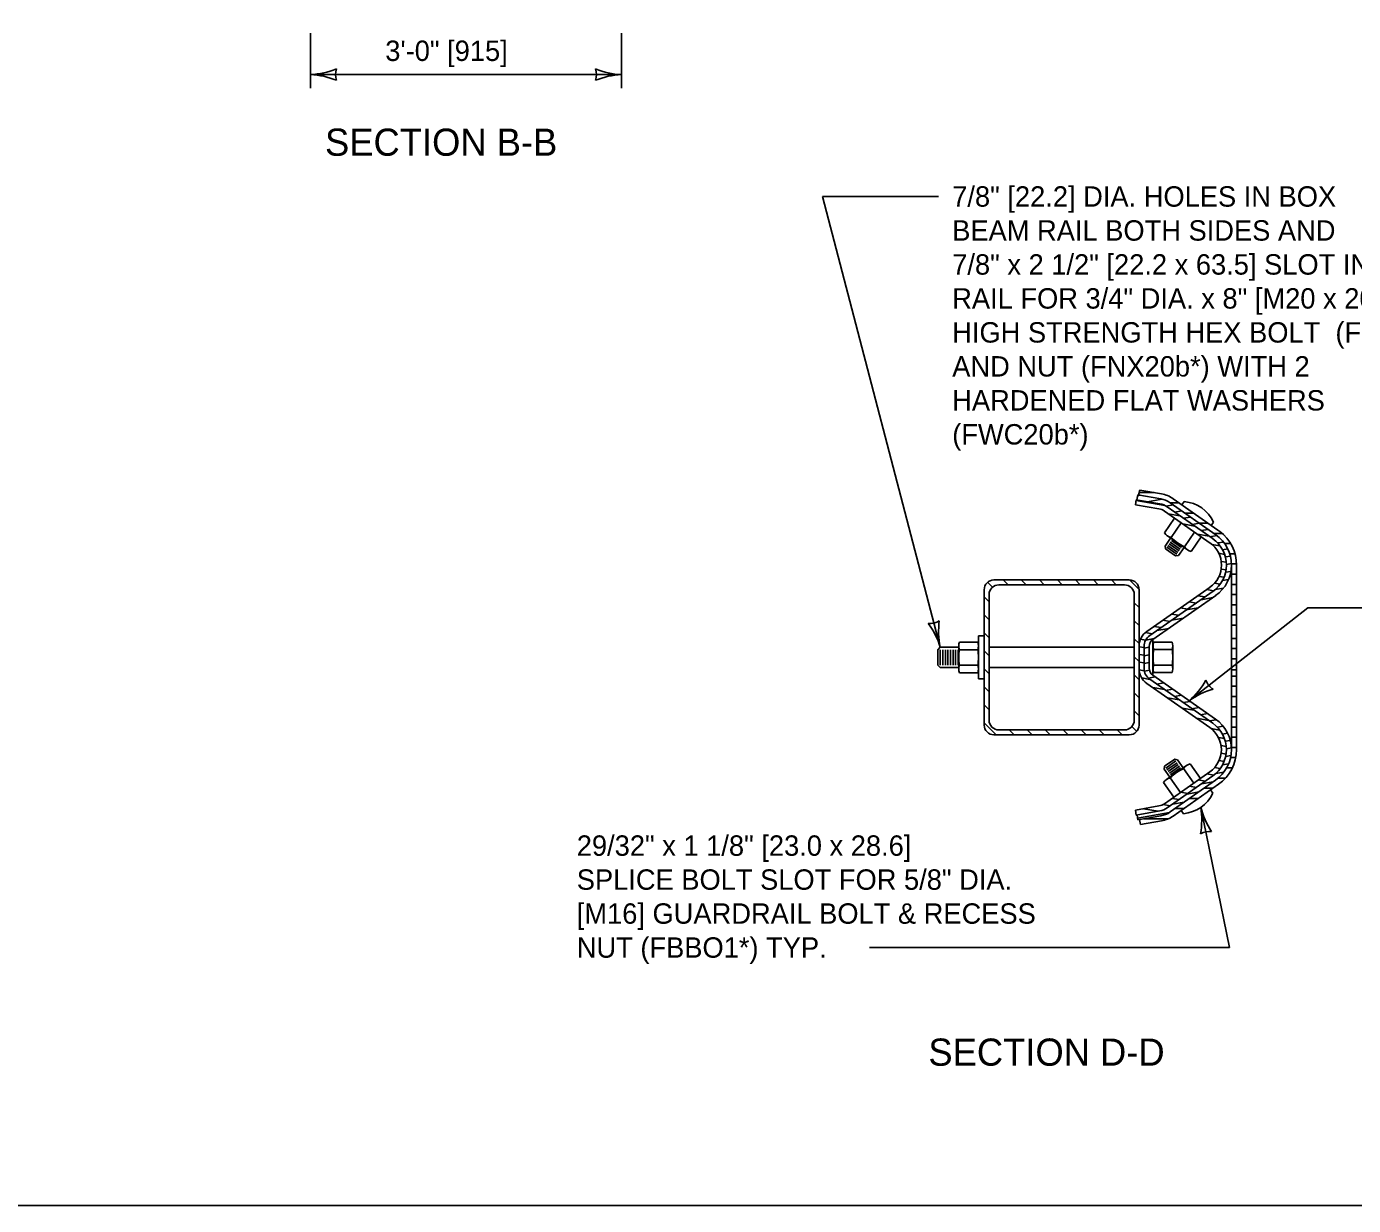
# Model space of a CAD drawing. Extents: x 49991.4 to 50021, y 49987.6 to 50011.4.
# Drawn here: x 50005.459 to 50009.364, y 49987.799 to 49991.269 of the extents above; entities that cross this region are included whole.
import ezdxf

# ---------------------------------------------------------------- set-up
doc = ezdxf.new("R2010")
doc.units = 0
for name, color, linetype in [('Level 1', 7, 'Continuous'), ('Level 2', 7, 'Continuous'), ('Level 3', 7, 'Continuous')]:
    doc.layers.add(name, color=color, linetype=linetype)

msp = doc.modelspace()

# ---------------------------------------------------------------- linework, layer by layer
at = {"layer": 'Level 1'}
for p, q in [((50008.7248, 49989.876), (50008.7222, 49989.8614)), ((50008.7244, 49989.874), (50008.8085, 49989.8592)), ((50008.7248, 49989.876), (50008.7941, 49989.8639)), ((50008.7293, 49989.8902), (50008.7268, 49989.8756)), ((50008.7288, 49989.8877), (50008.7362, 49989.889)), ((50008.7293, 49989.8902), (50008.7967, 49989.8785)), ((50008.7318, 49989.8898), (50008.7349, 49989.9043)), ((50008.7333, 49989.8968), (50008.7777, 49989.8968)), ((50008.7349, 49989.9043), (50008.7992, 49989.893)), ((50008.7576, 49989.8702), (50008.8, 49989.8777)), ((50008.8332, 49989.879), (50008.9647, 49989.7867)), ((50008.7222, 49989.8614), (50008.7916, 49989.8493)), ((50008.8077, 49989.8426), (50008.9421, 49989.7483)), ((50008.8123, 49989.8573), (50008.8332, 49989.861)), ((50008.8162, 49989.8548), (50008.9507, 49989.7604)), ((50008.8189, 49989.8348), (50008.8533, 49989.8287)), ((50008.8247, 49989.8669), (50008.9592, 49989.7725)), ((50008.8248, 49989.8668), (50008.8506, 49989.8668)), ((50008.8383, 49989.8393), (50008.8589, 49989.8429)), ((50008.8662, 49989.8704), (50008.8593, 49989.8607)), ((50008.8676, 49989.8368), (50008.8933, 49989.8368)), ((50008.8376, 49989.8216), (50008.8075, 49989.7786)), ((50008.8271, 49989.7648), (50008.8572, 49989.8078)), ((50008.8619, 49989.8046), (50008.8963, 49989.7985)), ((50008.864, 49989.8212), (50008.8846, 49989.8249)), ((50008.8898, 49989.8032), (50008.9103, 49989.8068)), ((50008.9104, 49989.8068), (50008.9361, 49989.8068)), ((50008.9523, 49989.8102), (50008.9454, 49989.8003)), ((50008.8094, 49989.7394), (50008.826, 49989.7632)), ((50008.8751, 49989.7289), (50008.8163, 49989.7701)), ((50008.8575, 49989.735), (50008.828, 49989.7556)), ((50008.8665, 49989.7373), (50008.8965, 49989.7803)), ((50008.9162, 49989.7665), (50008.8862, 49989.7236)), ((50008.905, 49989.7744), (50008.9393, 49989.7683)), ((50008.9155, 49989.7851), (50008.9361, 49989.7887)), ((50008.9413, 49989.7671), (50008.9616, 49989.7707)), ((50008.9532, 49989.7768), (50008.9776, 49989.7768)), ((50008.9592, 49989.7725), (50008.9585, 49989.7731)), ((50008.9647, 49989.7867), (50008.9703, 49989.7829)), ((50008.8094, 49989.7394), (50008.8108, 49989.731)), ((50008.8403, 49989.7104), (50008.8108, 49989.731)), ((50008.8438, 49989.7153), (50008.8143, 49989.736)), ((50008.8472, 49989.7202), (50008.8177, 49989.7409)), ((50008.8506, 49989.7251), (50008.8212, 49989.7458)), ((50008.8541, 49989.73), (50008.8246, 49989.7507)), ((50008.8487, 49989.7119), (50008.8654, 49989.7357)), ((50008.9473, 49989.7444), (50008.9712, 49989.7401)), ((50008.9644, 49989.7486), (50008.9812, 49989.7515)), ((50008.9675, 49989.7182), (50008.9846, 49989.7152)), ((50008.9789, 49989.7285), (50008.9941, 49989.7312)), ((50008.985, 49989.7468), (50009.0024, 49989.7468)), ((50008.9999, 49989.7168), (50009.0153, 49989.7168)), ((50008.8487, 49989.7119), (50008.8403, 49989.7104)), ((50008.9747, 49989.6943), (50008.9897, 49989.6917)), ((50008.9872, 49989.7074), (50009.0017, 49989.7099)), ((50008.9903, 49989.6854), (50009.0049, 49989.6879)), ((50009.0051, 49989.6834), (50009.0049, 49989.1403)), ((50009.0051, 49989.6868), (50009.0197, 49989.6868)), ((50009.0199, 49989.6834), (50009.0197, 49989.1403)), ((50008.7043, 49989.6399), (50008.3059, 49989.6399)), ((50008.3478, 49989.6255), (50008.3334, 49989.6399)), ((50008.4008, 49989.6255), (50008.3864, 49989.6399)), ((50008.4539, 49989.6255), (50008.4395, 49989.6399)), ((50008.5069, 49989.6255), (50008.4925, 49989.6399)), ((50008.5599, 49989.6255), (50008.5455, 49989.6399)), ((50008.613, 49989.6255), (50008.5986, 49989.6399)), ((50008.666, 49989.6255), (50008.6516, 49989.6399)), ((50008.733, 49989.6115), (50008.7046, 49989.6399)), ((50008.9682, 49989.6503), (50008.9831, 49989.6477)), ((50008.9746, 49989.6718), (50008.9891, 49989.6692)), ((50008.9787, 49989.6381), (50008.9964, 49989.6413)), ((50008.9879, 49989.6623), (50009.0034, 49989.6651)), ((50009.0051, 49989.6568), (50009.0199, 49989.6568)), ((50008.2771, 49989.6111), (50008.2771, 49989.2127)), ((50008.3016, 49989.6187), (50008.2872, 49989.6331)), ((50008.6899, 49989.6255), (50008.3203, 49989.6255)), ((50008.7331, 49989.2127), (50008.7331, 49989.6111)), ((50008.9422, 49989.6188), (50008.7562, 49989.4886)), ((50008.9507, 49989.6066), (50008.7647, 49989.4765)), ((50008.932, 49989.6115), (50008.9524, 49989.6079)), ((50008.9549, 49989.6301), (50008.9715, 49989.6271)), ((50008.9574, 49989.6118), (50008.9817, 49989.6161)), ((50009.0051, 49989.6268), (50009.0199, 49989.6268)), ((50008.2915, 49989.5758), (50008.2771, 49989.5902)), ((50008.2915, 49989.5967), (50008.2915, 49989.2271)), ((50008.7187, 49989.2271), (50008.7187, 49989.5967)), ((50008.7331, 49989.5585), (50008.7187, 49989.5729)), ((50008.9592, 49989.5945), (50008.7732, 49989.4643)), ((50008.8804, 49989.5754), (50008.9009, 49989.5718)), ((50008.9062, 49989.5935), (50008.9267, 49989.5899)), ((50008.9154, 49989.5818), (50008.9497, 49989.5878)), ((50008.9585, 49989.5938), (50008.9592, 49989.5945)), ((50009.0051, 49989.5968), (50009.0199, 49989.5968)), ((50009.0051, 49989.5668), (50009.0199, 49989.5668)), ((50008.2915, 49989.5228), (50008.2771, 49989.5372)), ((50008.2771, 49989.2994), (50008.2771, 49989.5244)), ((50008.7331, 49989.5054), (50008.7187, 49989.5198)), ((50008.803, 49989.5213), (50008.8236, 49989.5177)), ((50008.8288, 49989.5393), (50008.8494, 49989.5357)), ((50008.8289, 49989.5214), (50008.8634, 49989.5274)), ((50008.8546, 49989.5574), (50008.8751, 49989.5538)), ((50008.8721, 49989.5516), (50008.9065, 49989.5576)), ((50009.0051, 49989.5368), (50009.0199, 49989.5368)), ((50008.2915, 49989.4697), (50008.2771, 49989.4841)), ((50008.7521, 49989.4851), (50008.772, 49989.4816)), ((50008.7772, 49989.5033), (50008.7978, 49989.4996)), ((50008.7857, 49989.4912), (50008.8203, 49989.4972)), ((50009.0051, 49989.5068), (50009.0199, 49989.5068)), ((50008.148, 49989.4419), (50008.1405, 49989.4344)), ((50008.2023, 49989.4419), (50008.148, 49989.4419)), ((50008.2023, 49989.4457), (50008.2023, 49989.3783)), ((50008.2582, 49989.4569), (50008.2042, 49989.4569)), ((50008.2601, 49989.4457), (50008.2601, 49989.3783)), ((50008.2606, 49989.4749), (50008.2771, 49989.4749)), ((50008.2606, 49989.3489), (50008.2606, 49989.4749)), ((50008.2915, 49989.4419), (50008.7187, 49989.4419)), ((50008.7331, 49989.4524), (50008.7187, 49989.4668)), ((50008.7331, 49989.4441), (50008.7331, 49989.4119)), ((50008.7331, 49989.4433), (50008.7479, 49989.4407)), ((50008.7374, 49989.4651), (50008.7524, 49989.4625)), ((50008.7479, 49989.4441), (50008.7479, 49989.4119)), ((50008.7479, 49989.4393), (50008.7627, 49989.4419)), ((50008.7527, 49989.4627), (50008.7771, 49989.4671)), ((50008.7627, 49989.4441), (50008.7627, 49989.4119)), ((50008.7738, 49989.3592), (50008.7738, 49989.4647)), ((50008.7743, 49989.4458), (50008.7743, 49989.3785)), ((50008.7762, 49989.4571), (50008.8303, 49989.4571)), ((50008.8321, 49989.4458), (50008.8321, 49989.3785)), ((50009.005, 49989.4678), (50009.0198, 49989.4678)), ((50008.1405, 49989.4344), (50008.1405, 49989.3894)), ((50008.148, 49989.4344), (50008.148, 49989.3894)), ((50008.1555, 49989.4344), (50008.1555, 49989.3894)), ((50008.163, 49989.4344), (50008.163, 49989.3894)), ((50008.1705, 49989.4344), (50008.1705, 49989.3894)), ((50008.178, 49989.4344), (50008.178, 49989.3894)), ((50008.1855, 49989.4344), (50008.1855, 49989.3894)), ((50008.193, 49989.4344), (50008.193, 49989.3894)), ((50008.2005, 49989.4344), (50008.2005, 49989.3894)), ((50008.2583, 49989.4346), (50008.2041, 49989.4346)), ((50008.2915, 49989.4167), (50008.2771, 49989.4311)), ((50008.733, 49989.3995), (50008.7187, 49989.4138)), ((50008.7331, 49989.4207), (50008.7479, 49989.4181)), ((50008.7331, 49989.4119), (50008.7331, 49989.3798)), ((50008.7479, 49989.4167), (50008.7627, 49989.4193)), ((50008.7479, 49989.4119), (50008.7479, 49989.3798)), ((50008.7627, 49989.4119), (50008.7627, 49989.3798)), ((50008.7761, 49989.4348), (50008.8303, 49989.4348)), ((50009.005, 49989.4378), (50009.0198, 49989.4378)), ((50009.005, 49989.4078), (50009.0198, 49989.4078)), ((50008.148, 49989.3819), (50008.1405, 49989.3894)), ((50008.2023, 49989.3819), (50008.148, 49989.3819)), ((50008.2583, 49989.3893), (50008.2041, 49989.3893)), ((50008.2582, 49989.3669), (50008.2042, 49989.3669)), ((50008.2915, 49989.3637), (50008.2771, 49989.3781)), ((50008.2915, 49989.3819), (50008.7187, 49989.3819)), ((50008.7331, 49989.3981), (50008.7479, 49989.3955)), ((50008.7334, 49989.3754), (50008.7485, 49989.3728)), ((50008.7479, 49989.3941), (50008.7627, 49989.3967)), ((50008.7487, 49989.3717), (50008.7633, 49989.3743)), ((50008.7761, 49989.3894), (50008.8303, 49989.3894)), ((50008.7762, 49989.3671), (50008.8303, 49989.3671)), ((50009.005, 49989.3749), (50009.0198, 49989.3749)), ((50008.2606, 49989.3489), (50008.2771, 49989.3489)), ((50008.2915, 49989.3106), (50008.2771, 49989.325)), ((50008.7331, 49989.3463), (50008.7187, 49989.3607)), ((50008.741, 49989.3515), (50008.7649, 49989.3473)), ((50008.7562, 49989.3353), (50008.9412, 49989.2058)), ((50008.7603, 49989.3511), (50008.7802, 49989.3547)), ((50008.7647, 49989.3474), (50008.9497, 49989.2179)), ((50008.7732, 49989.3596), (50008.9582, 49989.2301)), ((50008.7854, 49989.333), (50008.806, 49989.3366)), ((50009.005, 49989.3568), (50009.0198, 49989.3568)), ((50009.005, 49989.3268), (50009.0198, 49989.3268)), ((50008.7331, 49989.2933), (50008.7187, 49989.3077)), ((50008.7734, 49989.3232), (50008.808, 49989.3171)), ((50008.8111, 49989.3149), (50008.8318, 49989.3186)), ((50008.8166, 49989.293), (50008.8511, 49989.2869)), ((50008.8369, 49989.2969), (50008.8576, 49989.3005)), ((50009.005, 49989.2968), (50009.0198, 49989.2968)), ((50008.2915, 49989.2576), (50008.2771, 49989.272)), ((50008.7331, 49989.2403), (50008.7187, 49989.2547)), ((50008.8597, 49989.2628), (50008.8943, 49989.2567)), ((50008.8627, 49989.2788), (50008.8833, 49989.2825)), ((50008.8885, 49989.2608), (50008.9091, 49989.2644)), ((50008.9142, 49989.2427), (50008.9349, 49989.2464)), ((50009.0049, 49989.2668), (50009.0197, 49989.2668)), ((50008.3121, 49989.1839), (50008.2771, 49989.219)), ((50008.7262, 49989.1941), (50008.7118, 49989.2085)), ((50008.9028, 49989.2326), (50008.9374, 49989.2265)), ((50008.94, 49989.2247), (50008.9604, 49989.2283)), ((50008.9634, 49989.2062), (50008.9804, 49989.2092)), ((50009.0049, 49989.2368), (50009.0197, 49989.2368)), ((50009.0049, 49989.2068), (50009.0197, 49989.2068)), ((50008.3059, 49989.1839), (50008.7043, 49989.1839)), ((50008.3203, 49989.1983), (50008.6899, 49989.1983)), ((50008.3651, 49989.1839), (50008.3507, 49989.1983)), ((50008.4182, 49989.1839), (50008.4038, 49989.1983)), ((50008.4712, 49989.1839), (50008.4568, 49989.1983)), ((50008.5242, 49989.1839), (50008.5098, 49989.1983)), ((50008.5773, 49989.1839), (50008.5629, 49989.1983)), ((50008.6303, 49989.1839), (50008.6159, 49989.1983)), ((50008.6833, 49989.1839), (50008.6689, 49989.1983)), ((50008.9455, 49989.2025), (50008.9702, 49989.1982)), ((50008.9668, 49989.1762), (50008.984, 49989.1731)), ((50008.9782, 49989.1862), (50008.9934, 49989.1889)), ((50009.0049, 49989.1768), (50009.0197, 49989.1768)), ((50008.9743, 49989.1522), (50008.9894, 49989.1496)), ((50008.9745, 49989.1296), (50008.9891, 49989.1271)), ((50008.9868, 49989.1652), (50009.0012, 49989.1677)), ((50008.99, 49989.1432), (50009.0047, 49989.1457)), ((50009.0049, 49989.1468), (50009.0197, 49989.1468)), ((50008.8069, 49989.0829), (50008.8083, 49989.0913)), ((50008.8083, 49989.0913), (50008.8378, 49989.1119)), ((50008.8118, 49989.0863), (50008.8413, 49989.107)), ((50008.8138, 49989.0522), (50008.8726, 49989.0934)), ((50008.8152, 49989.0814), (50008.8447, 49989.102)), ((50008.8187, 49989.0765), (50008.8482, 49989.0971)), ((50008.8221, 49989.0716), (50008.8516, 49989.0922)), ((50008.8462, 49989.1104), (50008.8378, 49989.1119)), ((50008.8462, 49989.1104), (50008.8629, 49989.0866)), ((50008.9138, 49989.0558), (50008.8837, 49989.0987)), ((50008.9684, 49989.1081), (50008.9832, 49989.1055)), ((50008.979, 49989.096), (50008.9966, 49989.0991)), ((50008.9879, 49989.1202), (50009.0033, 49989.1229)), ((50009.0023, 49989.1168), (50009.0171, 49989.1168)), ((50008.8069, 49989.0829), (50008.8235, 49989.059)), ((50008.9413, 49989.0751), (50008.8077, 49988.9812)), ((50008.9498, 49989.063), (50008.8162, 49988.9691)), ((50008.8247, 49989.0575), (50008.8548, 49989.0144)), ((50008.9583, 49989.0508), (50008.8247, 49988.957)), ((50008.8255, 49989.0667), (50008.855, 49989.0873)), ((50008.864, 49989.085), (50008.8941, 49989.0419)), ((50008.9072, 49989.0511), (50008.9278, 49989.0475)), ((50008.9329, 49989.0692), (50008.9531, 49989.0656)), ((50008.9554, 49989.0878), (50008.9718, 49989.0849)), ((50008.9585, 49989.0698), (50008.9822, 49989.074)), ((50008.9661, 49989.0568), (50008.987, 49989.0568)), ((50008.9909, 49989.0868), (50009.0072, 49989.0868)), ((50008.8352, 49989.0006), (50008.8051, 49989.0437)), ((50008.9668, 49989.0387), (50008.8332, 49988.9448)), ((50008.8558, 49989.015), (50008.8764, 49989.0114)), ((50008.8741, 49989.0098), (50008.9085, 49989.0158)), ((50008.8815, 49989.0331), (50008.9021, 49989.0294)), ((50008.917, 49989.0399), (50008.9515, 49989.046)), ((50008.9242, 49989.0268), (50008.9499, 49989.0268)), ((50008.9498, 49989.0121), (50008.943, 49989.0219)), ((50008.7916, 49988.9746), (50008.7222, 49988.9624)), ((50008.8041, 49988.979), (50008.825, 49988.9753)), ((50008.8301, 49988.997), (50008.8507, 49988.9933)), ((50008.8312, 49988.9796), (50008.8656, 49988.9857)), ((50008.8815, 49988.9968), (50008.9072, 49988.9968)), ((50008.7222, 49988.9624), (50008.7248, 49988.9478)), ((50008.7941, 49988.96), (50008.7248, 49988.9478)), ((50008.727, 49988.9482), (50008.7296, 49988.9336)), ((50008.7287, 49988.9389), (50008.8223, 49988.9554)), ((50008.7967, 49988.9454), (50008.7296, 49988.9336)), ((50008.7347, 49988.9345), (50008.7372, 49988.9199)), ((50008.746, 49988.9666), (50008.7888, 49988.9591)), ((50008.7478, 49988.9368), (50008.8183, 49988.9368)), ((50008.8388, 49988.9668), (50008.8645, 49988.9668)), ((50008.8637, 49988.9519), (50008.857, 49988.9615)), ((50008.7992, 49988.9308), (50008.7372, 49988.9199)), ((50008.7991, 49988.9308), (50008.7992, 49988.9308))]:
    msp.add_line(p, q, dxfattribs=at)
msp.add_lwpolyline([(49999.3835, 49998.9992), (50016.7501, 49998.9992), (50016.7501, 49987.7988), (49999.3835, 49987.7988)], close=True, dxfattribs=at)
for centre, radius, start, end in [((50008.7849, 49989.8103), 0.0692, 54.9095, 80.2724), ((50008.7849, 49989.8103), 0.084, 54.9095, 80.2724), ((50008.7849, 49989.8103), 0.0396, 54.9095, 80.2724), ((50008.7849, 49989.8103), 0.0544, 54.9095, 80.2724), ((50008.8571, 49989.7658), 0.105, 24.9838, 85.0234), ((50008.8957, 49989.6835), 0.0946, 304.9981, 54.9506), ((50008.8957, 49989.6835), 0.1094, 304.9981, 54.9506), ((50008.8957, 49989.6835), 0.1242, 359.9729, 53.1175), ((50008.8957, 49989.6835), 0.0798, 304.9981, 54.9506), ((50008.3059, 49989.6111), 0.0288, 90, 180), ((50008.7043, 49989.6111), 0.0288, 0, 90), ((50008.3203, 49989.5967), 0.0288, 90, 180), ((50008.6899, 49989.5967), 0.0288, 0, 90), ((50008.7874, 49989.4441), 0.0543, 125.0223, 180), ((50008.7874, 49989.4441), 0.0395, 125.0223, 180), ((50008.7874, 49989.4441), 0.0247, 125.0223, 180), ((50008.7874, 49989.3798), 0.0543, 180, 234.9777), ((50008.7874, 49989.3798), 0.0395, 180, 234.9777), ((50008.7874, 49989.3798), 0.0247, 180, 234.9777), ((50008.3059, 49989.2127), 0.0288, 180, 270), ((50008.3203, 49989.2271), 0.0288, 180, 270), ((50008.6899, 49989.2271), 0.0288, 270, 0), ((50008.7043, 49989.2127), 0.0288, 270, 0), ((50008.8954, 49989.1404), 0.0946, 305.0648, 55.0156), ((50008.8954, 49989.1404), 0.1095, 305.0648, 55.0156), ((50008.8954, 49989.1404), 0.0798, 305.0648, 55.0156), ((50008.8954, 49989.1404), 0.1243, 305.0648, 359.973), ((50008.8547, 49989.0565), 0.105, 274.9368, 334.9764), ((50008.7849, 49989.0136), 0.0396, 279.7276, 305.0905), ((50008.7849, 49989.0136), 0.0544, 279.7276, 305.0905), ((50008.7849, 49989.0136), 0.0692, 279.7276, 305.0905), ((50008.7849, 49989.0136), 0.084, 279.7276, 305.0905)]:
    msp.add_arc(centre, radius, start, end, dxfattribs=at)
for centre, major_axis, start_param, end_param in [((50008.8249, 49989.7824), (-0.0198, 0.0139), 1.047198, 2.084746), ((50008.8797, 49989.7982), (-0.078, 0.0546), 1.315951, 1.825641), ((50008.8837, 49989.7413), (-0.0198, 0.0139), 1.056847, 2.094396), ((50008.2163, 49989.4457), (0, -0.0225), 4.188789, 5.226338), ((50008.2461, 49989.4457), (0, -0.0225), 1.056847, 2.094396), ((50008.7884, 49989.4459), (0, -0.0225), 4.188789, 5.226338), ((50008.8181, 49989.4459), (0, -0.0225), 1.056847, 2.094396), ((50008.2584, 49989.4119), (0, -0.09), 4.457545, 4.967234), ((50008.204, 49989.4119), (0, -0.09), 1.31595, 1.825641), ((50008.8305, 49989.4121), (0, -0.09), 4.457545, 4.967235), ((50008.776, 49989.4121), (0, -0.09), 1.315951, 1.825641), ((50008.2163, 49989.3782), (0, -0.0225), 4.198439, 5.235988), ((50008.2461, 49989.3782), (0, -0.0225), 1.047198, 2.084746), ((50008.7884, 49989.3784), (0, -0.0225), 4.198439, 5.235988), ((50008.8181, 49989.3784), (0, -0.0225), 1.047198, 2.084746), ((50008.8813, 49989.081), (0.0198, 0.0139), 1.047198, 2.084746), ((50008.8225, 49989.0399), (0.0198, 0.0139), 1.056847, 2.094396), ((50008.8773, 49989.0241), (0.078, 0.0546), 1.315951, 1.825641)]:
    msp.add_ellipse(centre, major_axis=major_axis, ratio=0.623816, start_param=start_param, end_param=end_param, dxfattribs=at)
at = {"layer": 'Level 3'}
for p, q in [((50006.2946, 49991.0873), (50006.2946, 49991.2487)), ((50007.2096, 49991.0873), (50007.2096, 49991.2487)), ((50006.2946, 49991.1273), (50007.2096, 49991.1273)), ((50008.1431, 49990.7685), (50007.8013, 49990.7685)), ((50007.8013, 49990.7685), (50008.148, 49989.4419)), ((50008.8804, 49989.2845), (50009.2298, 49989.5582)), ((50009.4528, 49989.5582), (50009.2298, 49989.5582)), ((50008.9996, 49988.558), (50008.9148, 49988.9705)), ((50007.9397, 49988.558), (50008.9996, 49988.558))]:
    msp.add_line(p, q, dxfattribs=at)
for centre, radius, start, end in [((50006.2831, 49991.36), 0.233, 272.8273, 292.0772), ((50006.2854, 49990.9051), 0.2223, 67.456, 87.6395), ((50006.4228, 49991.1273), 0.0548, 162.1388, 197.8612), ((50007.2187, 49991.3494), 0.2223, 247.456, 267.6395), ((50007.0813, 49991.1273), 0.0548, 342.1388, 17.8612), ((50007.221, 49990.8946), 0.233, 92.8273, 112.0772), ((50008.1155, 49989.566), 0.0548, 266.7844, 302.5067), ((50008.376, 49989.4897), 0.233, 172.5684, 191.8182), ((50007.9354, 49989.3769), 0.2223, 17.006, 37.1895), ((50008.7279, 49989.4606), 0.233, 310.9013, 330.1511), ((50008.9814, 49989.3636), 0.0548, 200.2128, 235.9351), ((50009.0102, 49989.104), 0.2223, 105.53, 125.7135), ((50008.6846, 49988.9348), 0.233, 349.5417, 8.7915), ((50009.1306, 49989.0242), 0.2223, 193.9793, 214.1628), ((50008.9406, 49988.8449), 0.0548, 83.7576, 119.48)]:
    msp.add_arc(centre, radius, start, end, dxfattribs=at)

# ---------------------------------------------------------------- texts
at = {"layer": 'Level 2'}
for s, height, p in [('3\'-0" [915]', 0.06, (50006.5145, 49991.1673)), ('SECTION B-B', 0.08, (50006.3372, 49990.8883)), ('7/8" [22.2] DIA. HOLES IN BOX', 0.06, (50008.1831, 49990.7385)), ('BEAM RAIL BOTH SIDES AND', 0.06, (50008.1831, 49990.6385)), ('7/8" x 2 1/2" [22.2 x 63.5] SLOT IN W-BEAM', 0.06, (50008.1831, 49990.5385)), ('RAIL FOR 3/4" DIA. x 8" [M20 x 203] ', 0.06, (50008.1831, 49990.4385)), ('HIGH STRENGTH HEX BOLT  (FBX20b*)', 0.06, (50008.1831, 49990.3385)), ('AND NUT (FNX20b*) WITH 2', 0.06, (50008.1831, 49990.2385)), ('HARDENED FLAT WASHERS', 0.06, (50008.1831, 49990.1385)), ('(FWC20b*)  ', 0.06, (50008.1831, 49990.0385)), ('SECTION D-D', 0.08, (50008.1129, 49988.2101))]:
    msp.add_text(s, height=height, dxfattribs=at).set_placement(p)
for s, p in [('29/32" x 1 1/8" [23.0 x 28.6]', (50007.0781, 49988.828)), ('SPLICE BOLT SLOT FOR 5/8" DIA.', (50007.0781, 49988.728)), ('[M16] GUARDRAIL BOLT & RECESS', (50007.0781, 49988.628)), ('NUT (FBBO1*) TYP.', (50007.0781, 49988.528))]:
    msp.add_text(s, height=0.06, rotation=360, dxfattribs=at).set_placement(p)

doc.saveas('drawing.dxf')
